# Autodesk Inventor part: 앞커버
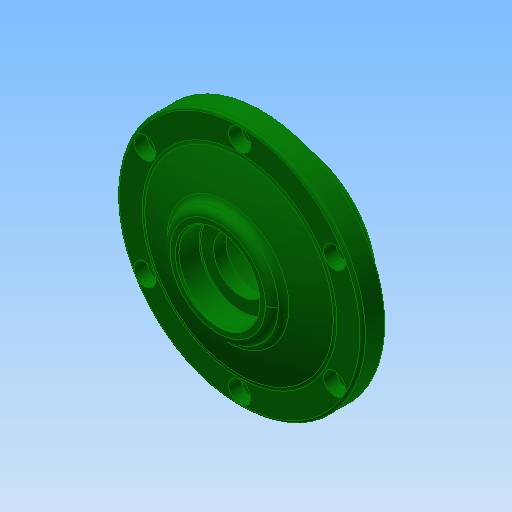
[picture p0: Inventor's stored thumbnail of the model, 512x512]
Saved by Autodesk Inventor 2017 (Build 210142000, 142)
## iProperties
Created: 2016-05
Part Number: 앞커버
Document SubType Name: Modeling
Designer: mduedu
Density: 2.71 g/cm^3
Material: 알루미늄 6061
Appearance: 진녹색
Author: mduedu
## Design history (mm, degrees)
sketch "스케치1"
  geometry: C1 r 31 at (0, 0); C2 r 45 at (0, 0); 1 further point
  constraints: 2 centre point, 2 coincident
  dimensions: "d33" = 90 diameter of C2; "d34" = 62 diameter of C1
extrude "돌출1" new body sketch "스케치1" distance "d0" = 8; taper "d1" = 0 deg
extrude "돌출2" join sketch "스케치1" distance "d2" = 8; taper "d3" = 0 deg; dims "d35" = 12, "d36" = 0
sketch "스케치5"
  geometry: L1 (-45, 8)-(45, 8) reference; L2 (0, 0)-(0, 15); L3 (-45, 0)-(45, 0) reference; L4 (35, 8)-(0, 8); A1 r 91 centre (0, -76) between (35, 8) and (0, 15)
  constraints: 4 end point, 3 point on line, 2 point on circle, 1 centre point, 1 midpoint, 1 perpendicular
  dimensions: "d37" = 35 distance from line of L2 L4.start; "d39" = 7 distance from line of L1 L2.end
revolve "회전2" sketch "스케치5" stored, may be unused: angle "d40" = 90 deg
node "작업 평면1"
sketch "스케치6"
  geometry: C1 r 20 at (0, 0); 1 further point
  constraints: 1 centre point, 1 coincident
  dimensions: "d42" = 40 diameter of C1
extrude "돌출4" join sketch "스케치6" stored distance "d43" = 10; taper "d44" = 0 deg
sketch "스케치4"
  geometry: L1 (0, -12)-(0, 16); L2 (-20, -12)-(-20, 0); L3 (-20, 0)-(-15, 0); L4 (-15, 0)-(-15, 3); L5 (-15, 3)-(-10, 3); L6 (-10, 3)-(-10, 7.5); L7 (-10, 7.5)-(-15, 7.5); L8 (-15, 7.5)-(-15, 16); L9 (31, -12)-(-31, -12) reference; L10 (-20, 16)-(20, 16) reference; 1 further point
  constraints: 16 end point, 6 parallel, 3 point on line, 2 midpoint, 1 perpendicular, 1 vertical
  dimensions: "d15" = 40 diameter of L2 L1; "d16" = 30 diameter of L8 L1; "d18" = 12 distance of L2.start L2.end; "d19" = 3 distance of L3.end L4.end; "d20" = 30 diameter of L4 L1; "d21" = 20 diameter of L6 L1; "d45" = 8.5 distance of L7.end L8.end
revolve "회전1" sketch "스케치4" stored, may be unused: angle "d22" = 90 deg
fillet "모깎기2" dims "d23" = 3
fillet "모깎기3" dims "d24" = 0.3
chamfer "모따기2" distance "d46" = 1; stored, may be unused: second distance "d47" = 2, angle "d48" = 45 deg
fillet "모깎기4" dims "d49" = 3
fillet "모깎기5" dims "d50" = 3
fillet "모깎기6" dims "d51" = 1
sketch "스케치7" dims "d52" = 80
  geometry: C1 r 35.595 at (0, 0) reference; C2 r 44 at (0, 0) reference; 7 further points
  constraints: 2 vertical alignment, 1 coincident, 9 other
  dimensions: "d55" = 360 deg dimension on C1.centre point (0, 40) (derived)
sketch "스케치8"
  geometry: 6 further points
  constraints: 6 other
hole "구멍2" sketch "스케치8" at (-34.641, 20), (-34.641, -20), (0, -40), (34.641, -20), (34.641, 20), (0, 40) diameter "d57" = 4.5; stored, may be unused: countersink angle "d61" = 90 deg, drill point angle "d63" = 0 deg; dims "d58" = 6, "d59" = 8, "d60" = 4.6, "d62" = 8
chamfer "모따기3" distance "d64" = 0.8; stored, may be unused: second distance "d65" = 2, angle "d66" = 30 deg
node "솔리드1"
other parameters: "d41" = 8
